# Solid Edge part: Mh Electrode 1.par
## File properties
Author: Dave
Template: Normal 2.par
Last saved by: Dave
Revision: 6
Application: Solid Edge
Accuracy: 0.990
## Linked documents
DKW001-01.027Squared Leg Foot.par
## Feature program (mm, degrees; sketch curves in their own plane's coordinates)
sketch for "ExtrudedCutout_1" plane through (35.3253, -4.1535, 2.52) normal (1, 0, 0) x-axis (0, 0, 1)
extrude "ExtrudedCutout_1" cut finite 107.95 along -normal
sketch for "ExtrudedCutout_5" plane through (4.4055, -4.4055, -5.115) normal (0, 0, -1) x-axis (1, 0, 0)
  line (-4.6403, 27.5196) -> (-4.6403, 19.9415)
  line (-27.5195, 27.9483) -> (-5.069, 27.9483)
  line (-27.9483, 6.1737) -> (-27.9483, 27.5195)
  arc centre (-27.5124, 6.1737) radius 0.4359 from (-27.8206, 5.8655) to (-27.9483, 6.1737) cw
  line (-26.272, 4.3169) -> (-27.8206, 5.8655)
  arc centre (-25.9688, 4.6202) radius 0.4289 from (-25.5675, 4.4688) to (-26.272, 4.3169) cw
  arc centre (-3.7598, -3.7598) radius 23.3085 from (-5.0455, 19.5132) to (-25.5675, 4.4688) ccw
extrude "ExtrudedCutout_5" cut finite 57.15 along -normal
sketch for "ExtrudedCutout_6" plane through (4.4055, -4.4055, -5.115) normal (0, 0, -1) x-axis (0, 1, 0)
  line (-27.9483, -2.4505) -> (-27.9483, 27.5195)
  line (-27.5196, 27.9483) -> (2.4505, 27.9483)
  line (2.8793, 27.5196) -> (2.8793, 19.9422)
  arc centre (2.4496, 19.9422) radius 0.4296 from (2.8793, 19.9422) to (2.4733, 19.5132) cw
  arc centre (3.7598, -3.7598) radius 23.3085 from (2.4733, 19.5132) to (-19.5132, -2.4733) ccw
  arc centre (-19.9422, -2.4496) radius 0.4296 from (-19.5132, -2.4733) to (-19.9422, -2.8793) cw
  line (-19.9422, -2.8793) -> (-27.5195, -2.8793)
extrude "ExtrudedCutout_6" cut finite 28.575 along -normal
sketch for "ExtrudedCutout_7" plane through (4.4055, -4.4055, -5.115) normal (0, 0, -1) x-axis (0, 1, 0)
  line (27.8206, 5.8655) -> (26.2721, 4.317)
  arc centre (27.5124, 6.1737) radius 0.4359 from (27.9483, 6.1737) to (27.8206, 5.8655) cw
  line (27.9483, 27.5196) -> (27.9483, 6.1737)
  line (5.069, 27.9483) -> (27.5195, 27.9483)
  line (4.6403, 19.9422) -> (4.6403, 27.5196)
  arc centre (5.0699, 19.9422) radius 0.4296 from (5.0462, 19.5132) to (4.6403, 19.9422) cw
  arc centre (3.7598, -3.7598) radius 23.3085 from (25.5675, 4.4688) to (5.0462, 19.5132) ccw
extrude "ExtrudedCutout_7" cut finite 212.725 along -normal
sketch for "ExtrudedCutout_9" plane through (4.4055, -4.4055, -5.115) normal (0, 0, -1) x-axis (-1, 0, 0)
  arc centre (3.7598, 3.7598) radius 20.3457 from (-0.0049, 23.7541) to (23.7541, -0.0049) ccw
  arc centre (24.8186, -0.2053) radius 1.0832 from (23.7541, -0.0049) to (25.5846, 0.5606) cw
  line (25.5846, 0.5606) -> (27.022, -0.8768)
  line (27.7544, -0.5734) -> (27.7544, 15.1317)
  arc centre (27.3254, 15.1317) radius 0.4291 from (27.7544, 15.1317) to (27.6288, 15.4351) ccw
  line (27.6288, 15.4351) -> (15.4351, 27.6288)
  arc centre (15.1317, 27.3254) radius 0.4291 from (15.4351, 27.6288) to (15.1317, 27.7544) ccw
  line (15.1317, 27.7544) -> (-0.5734, 27.7544)
  line (-0.8768, 27.022) -> (0.5606, 25.5846)
  arc centre (-0.2053, 24.8186) radius 1.0832 from (0.5606, 25.5846) to (-0.0049, 23.7541) cw
extrude "ExtrudedCutout_9" cut finite 38.1 along -normal
part copy "CopiedPart_3"  YScale = 1.008; ZScale = 1.008
Other named dimensions: "Offset_2": Distance = 0.075 mm
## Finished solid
Body 1: solid body, 146 faces, 363 edges, 218 vertices.
  Faces by surface: cylinder 60, offset 33, plane 32, swept 9, sphere 6, torus 5, cone 1
  Edges by curve: line 148, curve on surface 127, circle 54, intersection 25, spline 7, ellipse 2
Bounding box of the edges (mm; curved faces can reach further): 61.840 x 61.840 x 14.691, from (-26.5143, -35.3253, -5.115) to (35.3253, 26.5143, 9.576).
Cylindrical faces by radius (mm): R0.4289 x1, R0.429 x15, R0.4291 x2, R0.4296 x3, R0.4359 x2, R0.579 x30, R1.083 x1, R1.0832 x2, R20.3457 x1, R23.3085 x3
Conical faces (half-angle, radius in mm at the cone's reference point): 1 deg R20.337 x1
Toroidal faces (ring radius, tube radius in mm): R0.504 r0.579 x1, R21.1184 r0.579 x1, R22.7296 r0.579 x3
Spherical faces by radius (mm): R0.579 x6
Planar faces by outward normal: +x 4, +y 4, +z 1, -x 4, -y 4, -z 2, oblique 13
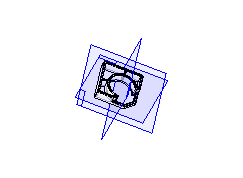
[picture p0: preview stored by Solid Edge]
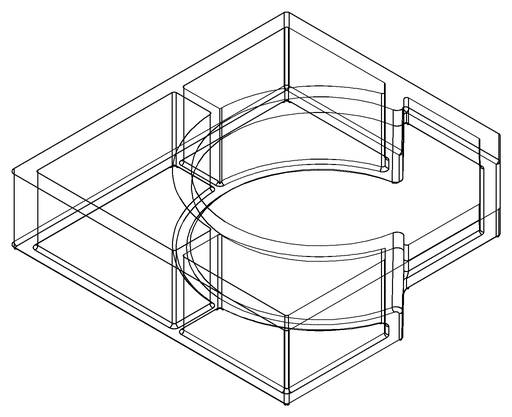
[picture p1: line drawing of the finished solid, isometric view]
